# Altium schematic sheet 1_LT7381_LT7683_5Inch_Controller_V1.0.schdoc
size 431 x 309 mm; Symbol: Sheet-Symbol_A3; Device: Sheet-Symbol_A3; @Page Name: LT7381/LT7683_5Inch_Controller_V1.0; @Create Date: 2022-11-14; @Page Count: 1; @Page No: 1; @Project Name: LT7381(LT7683)_5Inch_Controller; @Schematic Name: LT7381/LT7683_5Inch_Controller_V1.0; @Update Date: 2022-12-06; Company: LEVETOP; Page Size: A3; Version: V1.0
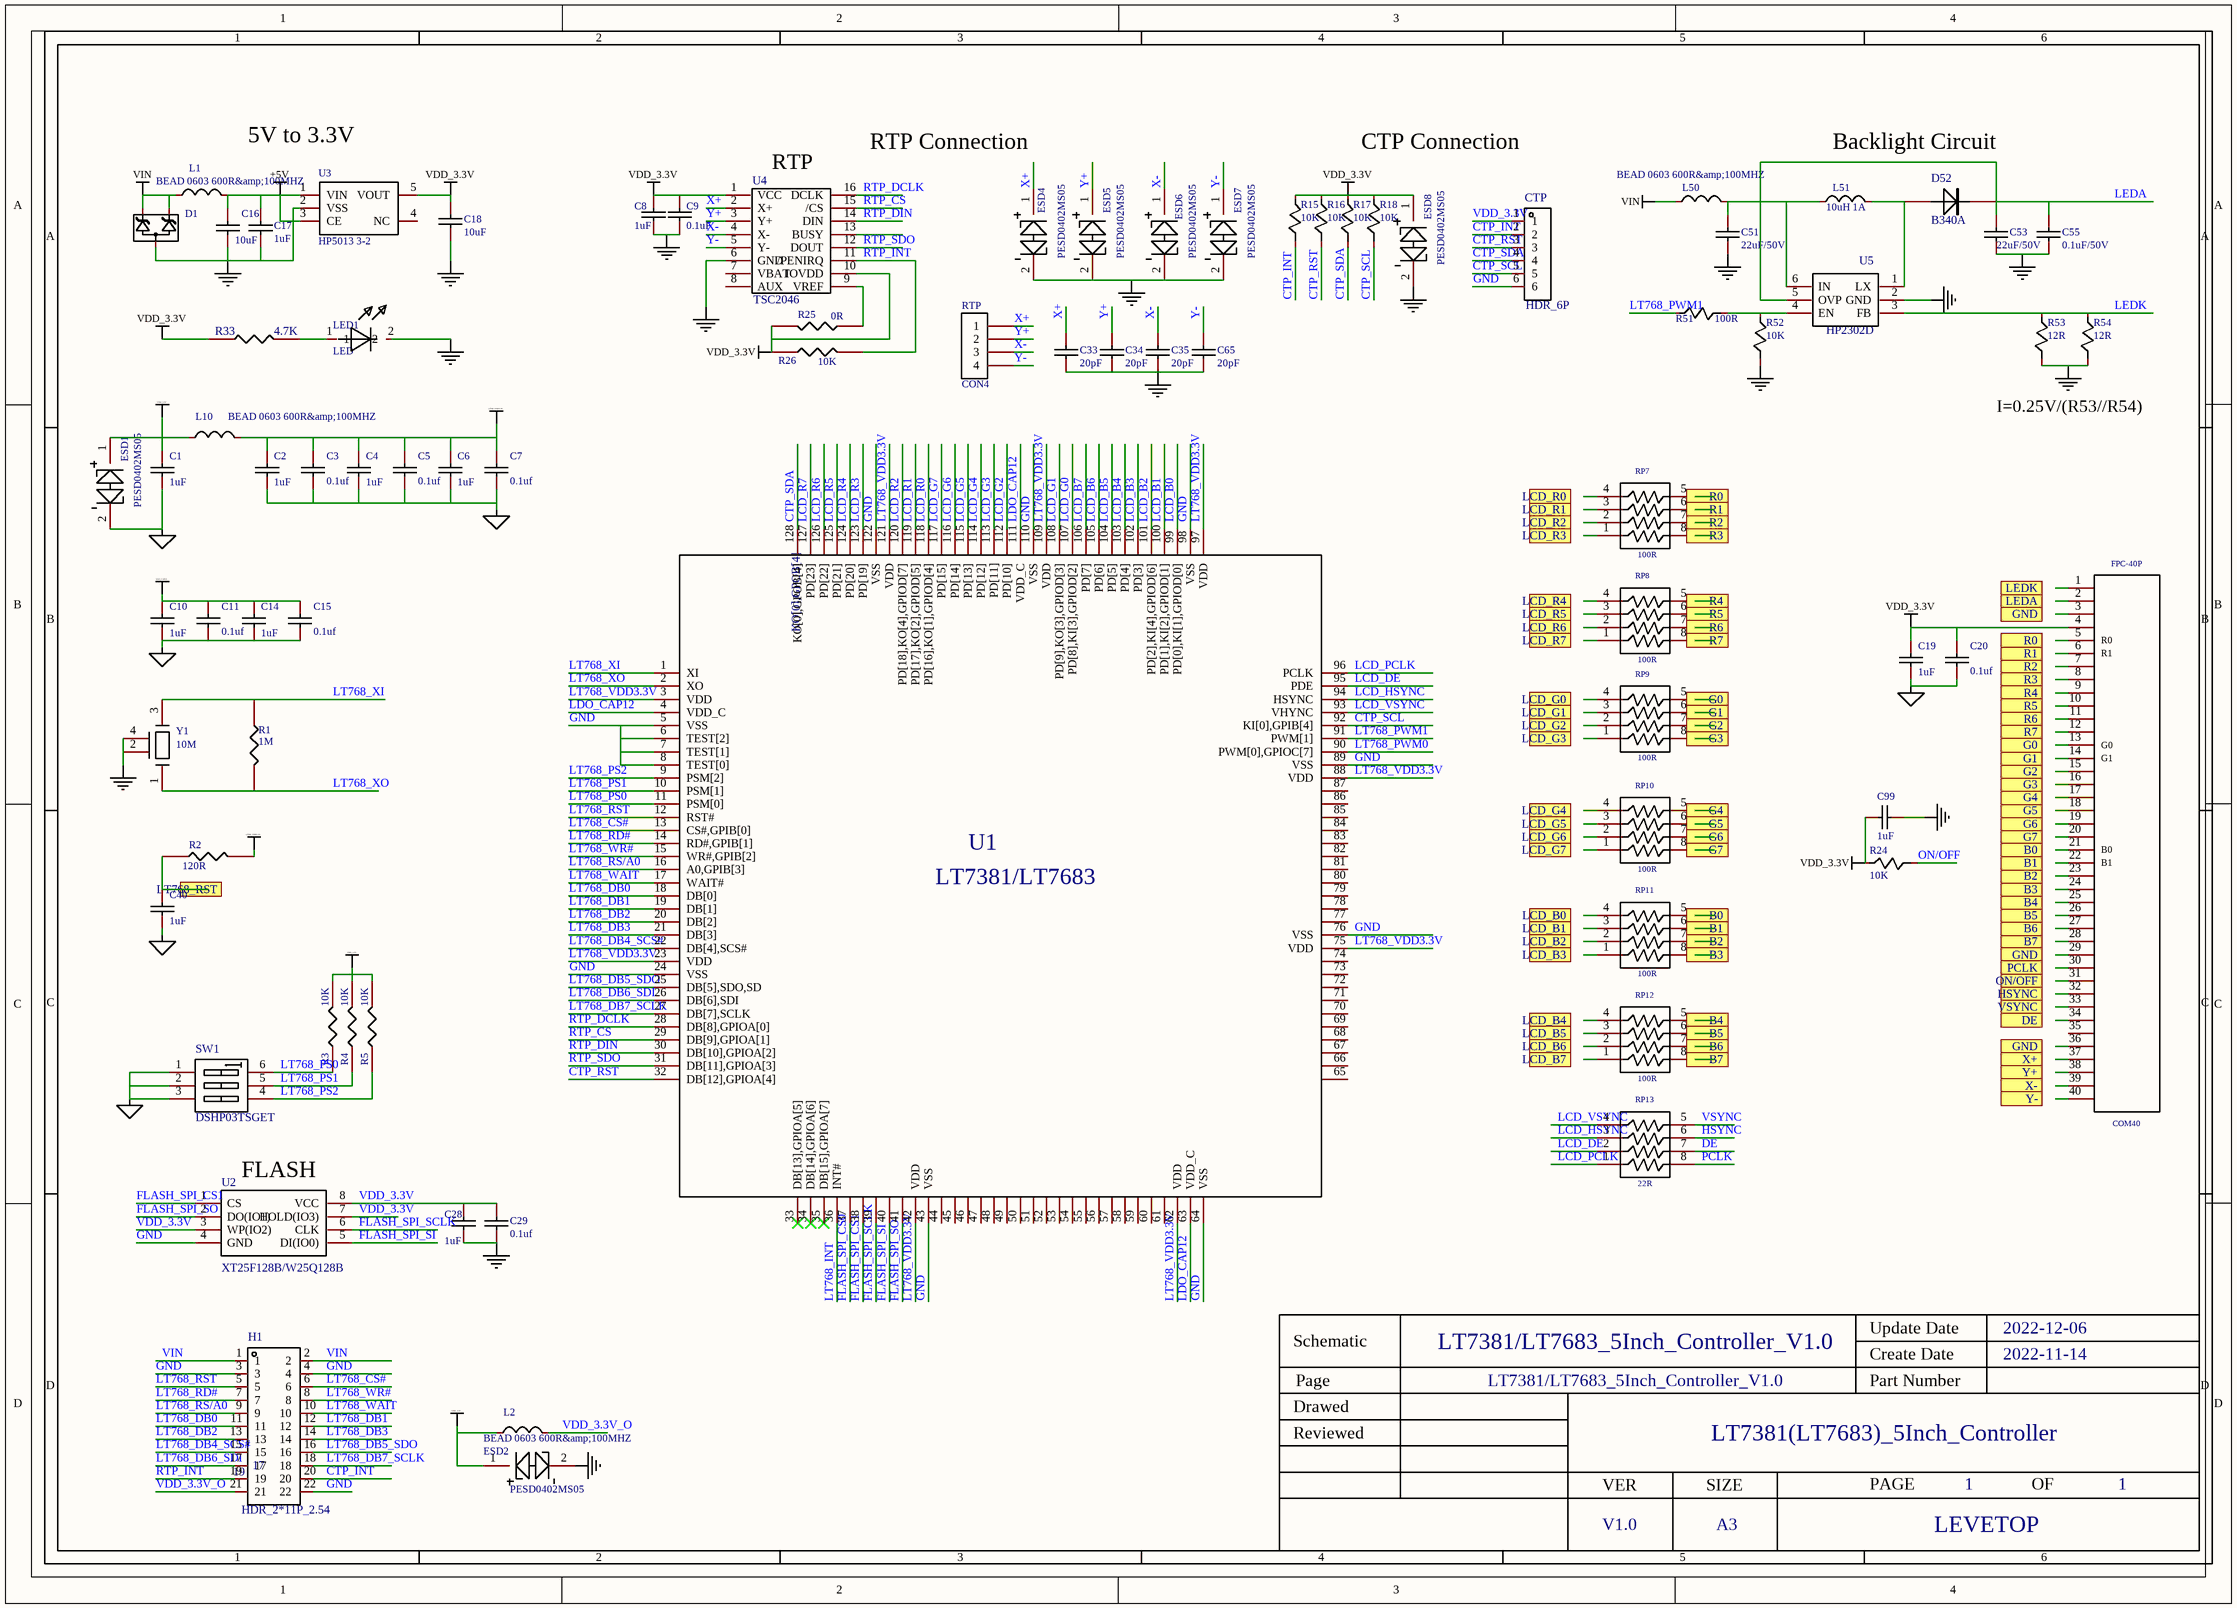
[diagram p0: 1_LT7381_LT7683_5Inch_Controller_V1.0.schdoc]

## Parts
C1  1uF  [C0603]
C2  1uF  [C0603]
C3  0.1uf  [C0603]
C4  1uF  [C0603]
C5  0.1uf  [C0603]
C6  1uF  [C0603]
C7  0.1uf  [C0603]
C8  1uF  [C0603]
C9  0.1uF  [C0603]
C10  1uF  [C0603]
C11  0.1uf  [C0603]
C14  1uF  [C0603]
C15  0.1uf  [C0603]
C16  10uF  [C0805]
C17  1uF  [C0603]
C18  10uF  [C0805]
C19  1uF  [C0603]
C20  0.1uf  [C0603]
C28  1uF  [C0603]
C29  0.1uf  [C0603]
C33  20pF  [C0603]
C34  20pF  [C0603]
C35  20pF  [C0603]
C40  1uF  [C0603]
C51  22uF/50V  [C0805_1]
C53  22uF/50V  [C0805_1]
C55  0.1uF/50V  [C0603]
C65  20pF  [C0603]
C99  1uF  [C0603]
CTP  HDR_6P  [SIP-6P]
D1  MMBZ5V6A  [SOT-23]  (value not drawn)
D52  B340A  [DO-214]
ESD1  PESD0402MS05  [ESD0402]
ESD2  PESD0402MS05  [ESD0402]
ESD4  PESD0402MS05  [ESD0402]
ESD5  PESD0402MS05  [ESD0402]
ESD6  PESD0402MS05  [ESD0402]
ESD7  PESD0402MS05  [ESD0402]
ESD8  PESD0402MS05  [ESD0402]
FPC-40P  COM40  [FPC40-0.5]
H1  NUMBER: 19  NAME: 17  [HDR-TH_22P-P2.54-V-M-R2-C11-S2.54]  (hidden comment: HDR_2*11P_2.54)
L1  BEAD 0603 600R&amp;100MHZ  [L0603]
L2  BEAD 0603 600R&amp;100MHZ  [L0603]
L10  BEAD 0603 600R&amp;100MHZ  [L0603]
L50  BEAD 0603 600R&amp;100MHZ  [L0603]
L51  10uH 1A  [IND8A]
LED1  LED  [0603LED]
R1  1M  [R0603_1]
R2  120R  [R0603]
R3  10K  [R0603]
R4  10K  [R0603]
R5  10K  [R0603]
R15  10K  [R0603]
R16  10K  [R0603]
R17  10K  [R0603]
R18  10K  [R0603]
R24  10K  [R0603]
R25  0R  [R0603]
R26  10K  [R0603]
R33  4.7K  [R0603]
R51  100R  [R0603]
R52  10K  [R0603]
R53  12R  [R0603]
R54  12R  [R0603]
RP7  value 100R  [8R4R]  (hidden comment: RP4)
RP8  value 100R  [8R4R]  (hidden comment: RP4)
RP9  value 100R  [8R4R]  (hidden comment: RP4)
RP10  value 100R  [8R4R]  (hidden comment: RP4)
RP11  value 100R  [8R4R]  (hidden comment: RP4)
RP12  value 100R  [8R4R]  (hidden comment: RP4)
RP13  value 22R  [8R4R]  (hidden comment: RP4)
RTP  CON4  [SIP-4P]
SW1  DSHP03TSGET  [SW-SMD_6P-L5.4-W5.4-P1.27-LS8.4]
U1  OldName: LT7381/LT7683  NAME: KO[0],GPOB[4]  [LQFP128L]  (hidden comment: LT768-136)
U2  XT25F128B/W25Q128B  [SOP-8A]
U3  HP5013 3-2  [SOT23-5]
U4  TSC2046  [TSSOP-16_L5.0-W4.4-P0.65-LS6.4-BL-1]
U5  HP2302D  [SOT23-6]
Y1  10M  [M3225_1]

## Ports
B0 (in), B1 (in), B2 (in), B3 (in), B4 (in), B5 (in), B6 (in), B7 (in), DE (in), G0 (in), G1 (in), G2 (in), G3 (in), G4 (in), G5 (in), G6 (in), G7 (in), GND (in), HSYNC (in), LCD_B0 (in), LCD_B1 (in), LCD_B2 (in), LCD_B3 (in), LCD_B4 (in), LCD_B5 (in), LCD_B6 (in), LCD_B7 (in), LCD_G0 (in), LCD_G1 (in), LCD_G2 (in), LCD_G3 (in), LCD_G4 (in), LCD_G5 (in), LCD_G6 (in), LCD_G7 (in), LCD_R0 (in), LCD_R1 (in), LCD_R2 (in), LCD_R3 (in), LCD_R4 (in), LCD_R5 (in), LCD_R6 (in), LCD_R7 (in), LEDA (in), LEDK (in), LT768_RST (in), ON/OFF (in), PCLK (in), R0 (in), R1 (in), R2 (in), R3 (in), R4 (in), R5 (in), R6 (in), R7 (in), VSYNC (in), X+ (in), X- (in), Y+ (in), Y- (in)

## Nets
+5V: C16.1 C17.1 L1.2 U3.1(VIN) U3.3(CE)
GND: C1.2 C2.2 C3.2 C4.2 C5.2 C6.2 C7.2 C8.2 C9.2 C10.2 C11.2 C14.2 C15.2 C16.2 C17.2 C18.2 C19.2 C20.2 C28.2 C29.2 C33.2 C34.2 C35.2 C40.2 C51.2 C53.2 C55.2 C65.2 C99.2 CTP.6 D1.3(CA) ESD1.2 ESD2.2 ESD4.2 ESD5.2 ESD6.2 ESD7.2 ESD8.2 H1.3 H1.4 H1.22 LED1.2 R52.2 R53.2 R54.2 SW1.1(A1) SW1.2(A2) SW1.3(A3) U1.5(VSS) U1.6(TEST[2]) U1.7(TEST[1]) U1.8(TEST[0]) U1.24(VSS) U1.43(VSS) U1.64(VSS) U1.76(VSS) U1.89(VSS) U1.98(VSS) U1.110(VSS) U1.122(VSS) U2.4(GND) U3.2(VSS) U4.6(GND) U5.2(GND) Y1.2 Y1.4
LDO_CAP12: C10.1 C11.1 C14.1 C15.1 U1.4(VDD_C) U1.63(VDD_C) U1.111(VDD_C)
LT768_VDD3.3V: C2.1 C3.1 C4.1 C5.1 C6.1 C7.1 L10.2 R2.2 U1.3(VDD) U1.23(VDD) U1.42(VDD) U1.62(VDD) U1.75(VDD) U1.88(VDD) U1.97(VDD) U1.109(VDD) U1.121(VDD)
VDD_3.3V: C1.1 C8.1 C9.1 C18.1 C19.1 C20.1 C28.1 C29.1 C99.1 CTP.1 ESD1.1 ESD2.1 ESD8.1 FPC-40P.4 L2.1 L10.1 R3.2 R4.2 R5.2 R15.1 R16.1 R17.1 R18.1 R24.1 R25.2 R26.1 R33.2 U2.3(WP(IO2)) U2.7(HOLD(IO3)) U2.8(VCC) U3.5(VOUT) U4.1(VCC) U4.10(IOVDD)
VIN: D1.1(C1) D1.2(C2) H1.1 H1.2 L1.1 L50.1
CTP_INT: CTP.2 H1.20 R15.2
CTP_RST: CTP.3 R16.2 U1.32(DB[12],GPIOA[4])
CTP_SCL: CTP.5 R18.2 U1.92(KI[0],GPIB[4])
CTP_SDA: CTP.4 R17.2 U1.128(KO[0],GPOB[4])
DE: RP13.7
FLASH_SPI_CS0: U1.37(SFCS[0]#,GPIOC[3])
FLASH_SPI_CS1: U1.38(SFCS[1]#,GPIOC[4]) U2.1(CS)
FLASH_SPI_SCLK: U1.39(SFCLK,GPIOC[0]) U2.6(CLK)
FLASH_SPI_SI: U1.40(SFDO,GPIOC[1]) U2.5(DI(IO0))
FLASH_SPI_SO: U1.41(SFDI,GPIOC[2]) U2.2(DO(IO1))
HSYNC: RP13.6
LCD_B0: U1.99(PD[0],KI[1],GPIOD[0])
LCD_B1: U1.100(PD[1],KI[2],GPIOD[1])
LCD_B2: U1.101(PD[2],KI[4],GPIOD[6])
LCD_B3: U1.102(PD[3])
LCD_B4: U1.103(PD[4])
LCD_B5: U1.104(PD[5])
LCD_B6: U1.105(PD[6])
LCD_B7: U1.106(PD[7])
LCD_DE: RP13.2 U1.95(PDE)
LCD_G0: U1.107(PD[8],KI[3],GPIOD[2])
LCD_G1: U1.108(PD[9],KO[3],GPIOD[3])
LCD_G2: U1.112(PD[10])
LCD_G3: U1.113(PD[11])
LCD_G4: U1.114(PD[12])
LCD_G5: U1.115(PD[13])
LCD_G6: U1.116(PD[14])
LCD_G7: U1.117(PD[15])
LCD_HSYNC: RP13.3 U1.94(HSYNC)
LCD_PCLK: RP13.1 U1.96(PCLK)
LCD_R0: U1.118(PD[16],KO[1],GPIOD[4])
LCD_R1: U1.119(PD[17],KO[2],GPIOD[5])
LCD_R2: U1.120(PD[18],KO[4],GPIOD[7])
LCD_R3: U1.123(PD[19])
LCD_R4: U1.124(PD[20])
LCD_R5: U1.125(PD[21])
LCD_R6: U1.126(PD[22])
LCD_R7: U1.127(PD[23])
LCD_VSYNC: RP13.4 U1.93(VHYNC)
LEDA: C53.1 C55.1 D52.2(K) U5.5(OVP)
LEDK: R53.1 R54.1 U5.3(FB)
LT768_CS#: H1.6 U1.13(CS#,GPIB[0])
LT768_DB0: H1.11 U1.18(DB[0])
LT768_DB1: H1.12 U1.19(DB[1])
LT768_DB2: H1.13 U1.20(DB[2])
LT768_DB3: H1.14 U1.21(DB[3])
LT768_DB4_SCS#: H1.15 U1.22(DB[4],SCS#)
LT768_DB5_SDO: H1.16 U1.25(DB[5],SDO,SD)
LT768_DB6_SDI: H1.17 U1.26(DB[6],SDI)
LT768_DB7_SCLK: H1.18 U1.27(DB[7],SCLK)
LT768_INT: U1.36(INT#)
LT768_PS0: R3.1 SW1.6(B1) U1.11(PSM[0])
LT768_PS1: R4.1 SW1.5(B2) U1.10(PSM[1])
LT768_PS2: R5.1 SW1.4(B3) U1.9(PSM[2])
LT768_PWM0: U1.90(PWM[0],GPIOC[7])
LT768_PWM1: R51.1 U1.91(PWM[1])
LT768_RD#: H1.7 U1.14(RD#,GPIB[1])
LT768_RS/A0: H1.9 U1.16(A0,GPIB[3])
LT768_RST: H1.5 U1.12(RST#)
LT768_RST: C40.1 R2.1 ; port LT768_RST  [a separate net that carries the same name]
LT768_WAIT: H1.10 U1.17(WAIT#)
LT768_WR#: H1.8 U1.15(WR#,GPIB[2])
LT768_XI: R1.1 U1.1(XI) Y1.3
LT768_XO: R1.2 U1.2(XO) Y1.1
ON/OFF: R24.2
PCLK: RP13.8
RTP_CS: U1.29(DB[9],GPIOA[1]) U4.15(/CS)
RTP_DCLK: U1.28(DB[8],GPIOA[0]) U4.16(DCLK)
RTP_DIN: U1.30(DB[10],GPIOA[2]) U4.14(DIN)
RTP_INT: H1.19 R26.2 U4.11(/PENIRQ)
RTP_SDO: U1.31(DB[11],GPIOA[3]) U4.12(DOUT)
VDD_3.3V_O: H1.21 L2.2
VSYNC: RP13.5
X+: C33.1 ESD4.1 RTP.1 U4.2(X+)
X-: C35.1 ESD6.1 RTP.3 U4.4(X-)
Y+: C34.1 ESD5.1 RTP.2 U4.3(Y+)
Y-: C65.1 ESD7.1 RTP.4 U4.5(Y-)
NetC51_1: C51.1 L50.2 L51.1 U5.6(IN)
NetD52_1: D52.1(A) L51.2 U5.1(LX)
NetLED1_1: LED1.1 R33.1
NetR25_1: R25.1 U4.9(VREF)
NetR51_2: R51.2 R52.1 U5.4(EN)

Not connected (* = marked no-connect by the designer): FPC-40P 1 2 3 5 6 7 8 9 10 11 12 13 14 15 16 17 18 19 20 21 22 23 24 25 26 27 28 29 30 31 32 33 34 35 36 37 38 39 40; RP7 1 2 3 4 5 6 7 8; RP8 1 2 3 4 5 6 7 8; RP9 1 2 3 4 5 6 7 8; RP10 1 2 3 4 5 6 7 8; RP11 1 2 3 4 5 6 7 8; RP12 1 2 3 4 5 6 7 8; U1 33(DB[13],GPIOA[5])* 34(DB[14],GPIOA[6])* 35(DB[15],GPIOA[7])* 44(NC) 45(NC) 46(NC) 47(NC) 48(NC) 49(NC) 50(NC) 51(NC) 52(NC) 53(NC) 54(NC) 55(NC) 56(NC) 57(NC) 58(NC) 59(NC) 60(NC) 61(NC) 65(NC) 66(NC) 67(NC) 68(NC) 69(NC) 70(NC) 71(NC) 72(NC) 73(NC) 74(NC) 77(NC) 78(NC) 79(NC) 80(NC) 81(NC) 82(NC) 83(NC) 84(NC) 85(NC) 86(NC) 87(NC); U3 4(NC); U4 7(VBAT) 8(AUX) 13(BUSY)

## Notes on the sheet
- 5V to 3.3V
- (near U4) RTP
- RTP Connection
- CTP Connection
- Backlight Circuit
- I=0.25V/(R53//R54)
- (near FPC-40P) R0
- (near FPC-40P) R1
- (near FPC-40P) G0
- (near FPC-40P) G1
- (near FPC-40P) B0
- (near FPC-40P) B1
- (near U2) FLASH

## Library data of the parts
C1-C7 C10 C11 C14 C15 C19 C20 C28 C29 C40 C55 C99 = CAP_C0603: Capacitor; Symbol: CAP; Add into BOM: yes
C8 C9 C33-C35 C65 = CAP_C0603: Capacitor; Symbol: CAP; Add into BOM: yes; Origin Footprint 2: 0603
C16 C18 = CAP_CAP_0805: Capacitor; Symbol: CAP; Origin Footprint 2: 0805; Add into BOM: yes
C17 = CAP_C0603: Capacitor; Symbol: CAP; Origin Footprint 2: 0603; Add into BOM: yes
C51 C53 = CAP_C0805: Capacitor; Symbol: CAP; Origin Footprint: C0805; Add into BOM: yes
CTP = 排针 2.54mm 1*60P直排针: Connector; Symbol: Header-Female-2.54_1x6; Add into BOM: yes
D1 = ESD7C3.3DT5G: Diode, Dual ESD Protection, 3.3V, SOT-723; Add into BOM: yes
D52 = DIODE(1): Diode; Pin Type: IN; Add into BOM: yes; Origin Footprint 2: SOD-323
ESD1 ESD2 ESD4-ESD8 = ESD5621W15_ESD0402: ESD; Add into BOM: yes
FPC-40P = COM40: Connector; Add into BOM: yes
H1 = CS-1106-2*11B: Header; Manufacturer: CST(永丰盈); Add into BOM: yes; Pitch: 2.54mm; Pin Structure: 2x11P; Circluar Pins/Square Pins: 方针; Current Rating (Max): 3A; Voltage Rating (Max): 250V
L1 L2 L10 = IND_R0603: BEAD; Symbol: IND; Origin Footprint: R0603; Add into BOM: yes
L50 = IND: BEAD; Origin Footprint: R0603; Add into BOM: yes
L51 = IND_IND8A: Industance; Symbol: IND; Add into BOM: yes
LED1 = LED_1: Add into BOM: yes
R1 = RES1: Resistance; Origin Footprint: R0603; Add into BOM: yes
R2-R5 R33 = RES1_R0603: Resistance; Symbol: RES1; Add into BOM: yes
R15-R18 R24 R51-R54 = RES_R0603: Resistance; Symbol: RES; Add into BOM: yes
R25 R26 = RES1_R0603: Resistance; Symbol: RES1; Add into BOM: yes; Origin Footprint 2: 0603
RP7-RP13 = RP4: Resistor Packs; Symbol: RP-4; Add into BOM: yes
RTP = CON4: Connector; Add into BOM: yes
SW1 = DSHP03TSGET: Switch; Manufacturer: YE; Symbol: DSHP03TSGER; Add into BOM: yes; Circuit: 单刀单掷; Number of Positions: 3
U1 = LT768-136: IC; Symbol: LQFP128; Add into BOM: yes
U2 = W25Q64BVSIG: IC; Add into BOM: yes
U3 = HP5013 3-2: IC; Add into BOM: yes
U4 = TSC2046: IC; PCB DECAL: TSSOP-16; Add into BOM: yes
U5 = G5126: IC; Add into BOM: yes
Y1 = CRY_SJK: XTAL; Origin Footprint: M3225; Add into BOM: yes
